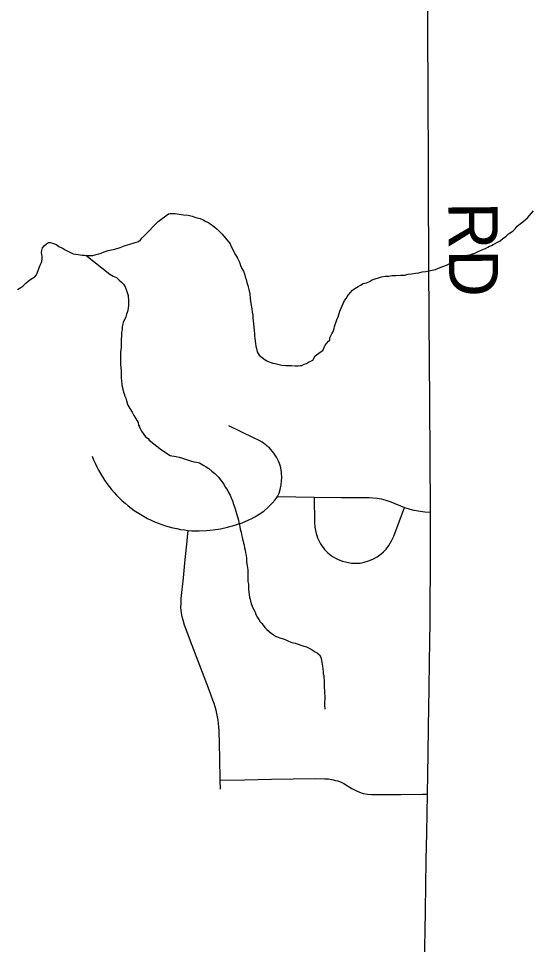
# Model space of a CAD drawing. Extents: x 103424 to 286016, y 38711 to 110967.
# Drawn here: x 131934 to 135093, y 58236 to 63924 of the extents above; entities that cross this region are included whole.
import ezdxf

# ---------------------------------------------------------------- set-up
doc = ezdxf.new("R2010")
doc.units = 0
for name, color, linetype in [('GM_X_County_Road', 7, 'Continuous'), ('GM_X_County_Road_Text', 7, 'Continuous'), ('GM_X_Minor_River', 7, 'Continuous'), ('GM_X_Township_Road', 7, 'Continuous')]:
    doc.layers.add(name, color=color, linetype=linetype)

msp = doc.modelspace()

# ---------------------------------------------------------------- linework, layer by layer
at = {"layer": 'GM_X_County_Road'}
msp.add_lwpolyline([(134429, 58147.9), (134432.1, 58313), (134434.6, 58452.5), (134437.2, 58591.9), (134440, 58757), (134442.8, 58922), (134444.8, 59040.6), (134446.8, 59159.2), (134448.9, 59283.3), (134451, 59407.3), (134453.7, 59572.4), (134455.7, 59690.3), (134457.7, 59808.2), (134460, 59973.2), (134461.8, 60095.1), (134463.5, 60217.1), (134464.5, 60363.3), (134465.4, 60509.6), (134466, 60621.2), (134466.7, 60732.8), (134465.5, 60892.6), (134463.9, 61242.9), (134463.2, 61345.7), (134462.4, 61448.6), (134461.1, 61613.7), (134459.7, 61778.7), (134458.8, 61890.9), (134457.9, 62003.1), (134457, 62168.2), (134456.1, 62333.2), (134455.4, 62448.8), (134454.8, 62564.3), (134454.3, 62729.4), (134453.9, 62894.5), (134453.4, 63059.5), (134452, 63420), (134451.1, 63576.4), (134450.3, 63732.7), (134448.5, 63892.5), (134446.7, 64052.2)], dxfattribs=at)
at = {"layer": 'GM_X_Minor_River'}
for points in [[(133937.8, 62191), (133949.7, 62205.4), (133953.5, 62215.6), (133961.3, 62225.9), (133971.2, 62238.2), (133987, 62254.7), (134000.9, 62265.1), (134010.9, 62271.4), (134020.9, 62277.7), (134034.8, 62286), (134052.8, 62296.5), (134072.9, 62301), (134090.9, 62309.5), (134106.9, 62317.9), (134165.1, 62337.3), (134187.3, 62341.9), (134209.5, 62342.3), (134229.6, 62344.8), (134251.9, 62345.3), (134284.1, 62348), (134306.4, 62348.5), (134328.5, 62353), (134350.7, 62355.5), (134372.8, 62360), (134395, 62362.5), (134415.1, 62367), (134437.3, 62369.5), (134455.4, 62373.9), (134475.5, 62378.4), (134495.6, 62382.9), (134515.7, 62391.4), (134541.7, 62400), (134563.8, 62408.6), (134587.8, 62421.2), (134611.8, 62431.8), (134635.8, 62442.5), (134659.9, 62453.1), (134681.9, 62461.6), (134701.9, 62470.1), (134718, 62476.6), (134738, 62483), (134754, 62491.5), (134778.1, 62500.1), (134792.1, 62506.4), (134804.2, 62510.7), (134818.1, 62519.1), (134828.1, 62525.4), (134840.1, 62529.7), (134850.1, 62536), (134864.1, 62542.3), (134878.1, 62550.7), (134894.1, 62559.1), (134909.9, 62573.6), (134929.9, 62586.2), (134945.7, 62600.6), (134961.7, 62611.1), (134973.6, 62619.4), (134985.5, 62631.8), (134999.3, 62648.2), (135017.2, 62662.8), (135033.1, 62675.2), (135047, 62687.6), (135060.9, 62700.1), (135098.3, 62743.3)], [(131928, 62259.7), (131948, 62272.1), (131960, 62280.4), (131977.8, 62298.9), (131993.8, 62311.3), (132003.7, 62319.5), (132019.7, 62329.9), (132031.7, 62336.1), (132043.6, 62350.5), (132066.8, 62409.4), (132072.6, 62421.7), (132076.5, 62431.8), (132078.2, 62450), (132078, 62462.2), (132077.8, 62474.3), (132075.6, 62486.4), (132077.4, 62498.5), (132081.2, 62514.7), (132091.1, 62527), (132105, 62539.4), (132117, 62547.6), (132129.1, 62547.9), (132143.3, 62544), (132155.4, 62540.2), (132169.6, 62534.4), (132181.9, 62524.5), (132196.2, 62516.6), (132208.4, 62510.8), (132220.6, 62502.9), (132232.8, 62497), (132245, 62491.2), (132257.2, 62485.3), (132269.4, 62479.4), (132283.6, 62475.6), (132299.8, 62473.9), (132324.1, 62470.2), (132338.2, 62470.5), (132354.4, 62468.7), (132370.5, 62469), (132380.6, 62469.1), (132390.7, 62469.3), (132410.8, 62473.7), (132426.9, 62478), (132440.9, 62482.3), (132459, 62490.6), (132485, 62499.1), (132525.3, 62507.9), (132557.4, 62518.5), (132589.5, 62529.1), (132617.6, 62537.7), (132671.8, 62554.7), (132683.7, 62565), (132693.6, 62577.3), (132705.5, 62589.6), (132792.5, 62676.8)], [(132792.5, 62676.8), (132855.2, 62724.8), (132865.3, 62727), (132877.4, 62727.3), (132895.6, 62725.7), (132920, 62722.1), (132948.3, 62718.7), (132976.7, 62715.3), (133001.1, 62709.8), (133023.5, 62702.2), (133049.9, 62694.7), (133068.3, 62687), (133084.6, 62677.3), (133100.9, 62671.6), (133111.2, 62663.7), (133123.5, 62653.9), (133140, 62642.1), (133154.4, 62630.3), (133168.8, 62616.5), (133183.3, 62600.7), (133197.8, 62584.8), (133214.4, 62565), (133226.8, 62551.1), (133235.1, 62539.2), (133241.5, 62523.2), (133250, 62505.2), (133258.5, 62487.2), (133266.9, 62473.3), (133273.2, 62461.3), (133279.4, 62451.3), (133285.8, 62439.4), (133292.1, 62427.4), (133298.6, 62407.3), (133307, 62389.3), (133315.5, 62371.4), (133321.9, 62355.3), (133326.3, 62337.3), (133332.8, 62321.3), (133337.2, 62303.2), (133343.7, 62283.1), (133348.2, 62259), (133354.8, 62232.9), (133357.5, 62204.7), (133362.2, 62174.5), (133366.9, 62140.3), (133369.4, 62120.1), (133373.8, 62102.1), (133374.1, 62085.9), (133379.4, 62029.5), (133381.9, 62007.3), (133384.3, 61987.2), (133384.6, 61973.1), (133386.9, 61961), (133387.3, 61942.9), (133389.7, 61926.8), (133392, 61910.7), (133396.4, 61896.6), (133400.8, 61876.5), (133413.4, 61856.6), (133431.9, 61840.9), (133450.4, 61827.1), (133460.6, 61821.3), (133474.9, 61815.5), (133485.1, 61811.7), (133497.3, 61807.9), (133511.5, 61804.2), (133527.8, 61800.5), (133552.1, 61795), (133576.4, 61793.5), (133610.8, 61792.2), (133633.1, 61790.7), (133653.3, 61791.2), (133665.4, 61793.4), (133675.5, 61793.7), (133689.5, 61800), (133703.5, 61804.4), (133715.5, 61812.7), (133729.5, 61819.1), (133743.5, 61825.4), (133757.1, 61852), (133786.9, 61874.8), (133804.9, 61885.3), (133818.3, 61917.9), (133838, 61942.6), (133848, 61948.8), (133847.7, 61963), (133859.3, 61987.4), (133865.1, 61997.7), (133869, 62007.8), (133872.8, 62020), (133876.5, 62032.2), (133880.3, 62044.4), (133886, 62060.7), (133891.7, 62079), (133897.5, 62091.2), (133903.3, 62105.5), (133908.9, 62125.8), (133916.6, 62144.2), (133922.4, 62158.4), (133930.1, 62176.8), (133937.8, 62191)], [(132347.4, 62469.5), (132495.5, 62353.8), (132515.9, 62342.1), (132536.3, 62332.3), (132552.7, 62316.4), (132567, 62304.5), (132579.3, 62292.6), (132589.7, 62276.6), (132596, 62258.5), (132606.7, 62222.3), (132606.9, 62212.2), (132609.1, 62198.1), (132609.4, 62179.9), (132609.8, 62161.8), (132608, 62147.6), (132606.2, 62131.4), (132602.4, 62119.2), (132596.5, 62107), (132592.8, 62090.8), (132585, 62072.5), (132577.2, 62058.2), (132575.4, 62046), (132571.6, 62029.8), (132569.9, 62011.6), (132566.1, 61995.4), (132566.5, 61975.2), (132564.8, 61952.9), (132565.2, 61928.7), (132563.6, 61902.4), (132560.1, 61874.1), (132560.6, 61841.8), (132561.3, 61803.4), (132561.7, 61777.1), (132564, 61763), (132564.2, 61748.9), (132564.4, 61734.7), (132564.8, 61714.5), (132567.1, 61698.4), (132569.5, 61674.2), (132571.8, 61654), (132576.1, 61640), (132578.3, 61627.9), (132582.5, 61617.9), (132586.8, 61603.8), (132593.1, 61591.8), (132597.4, 61575.7), (132605.9, 61549.5), (132618.3, 61529.5), (132632.8, 61505.5), (132643.3, 61485.5), (132653.6, 61469.5), (132662, 61453.5), (132668.2, 61443.5), (132670.5, 61425.3), (132676.7, 61415.3), (132680.9, 61405.3), (132689.3, 61389.3), (132714.1, 61355.3), (132730.4, 61343.5), (132736.6, 61333.5), (132811.9, 61273.7)], [(132811.9, 61273.7), (132864.7, 61239), (132876.9, 61237.2), (132891, 61235.5), (132903.2, 61233.7), (132921.5, 61230.1), (132941.8, 61222.5), (132966.3, 61214.9), (132990.7, 61207.4), (133011, 61201.8), (133029.3, 61198.1), (133045.5, 61194.4), (133055.8, 61188.6), (133072.1, 61178.8), (133086.4, 61171.1), (133102.9, 61159.3), (133121.4, 61143.6), (133139.9, 61129.8), (133154.3, 61116), (133164.7, 61104.1), (133173, 61092.2), (133181.3, 61082.3), (133195.8, 61064.4), (133204.3, 61046.4), (133216.8, 61030.6), (133225.2, 61012.6), (133233.7, 60996.6), (133240.1, 60980.6), (133248.6, 60960.6), (133255.1, 60940.5), (133263.6, 60918.5), (133270.1, 60898.5), (133285.5, 60842.3), (133287.8, 60826.2), (133292.1, 60814.1), (133294.4, 60802.1), (133296.7, 60788), (133301.2, 60769.9), (133303.5, 60753.8), (133307.9, 60737.8), (133310.2, 60725.7), (133314.5, 60713.7), (133316.7, 60701.6), (133321.1, 60689.6), (133323.4, 60673.5), (133325.7, 60659.4), (133328.2, 60641.3), (133332.5, 60625.2), (133334.9, 60609.1), (133335.3, 60588.9), (133337.6, 60574.9), (133339.9, 60562.8), (133340.2, 60550.7), (133342.5, 60538.6), (133342.9, 60518.4), (133343.2, 60506.3), (133343.6, 60484.1), (133344, 60466), (133346.4, 60449.9), (133346.7, 60435.7), (133347.1, 60417.6), (133349.4, 60401.5), (133351.8, 60383.4), (133354.2, 60369.3), (133356.4, 60357.2), (133358.7, 60345.2), (133365.2, 60325.1), (133373.7, 60305.1), (133382.1, 60289.1), (133388.5, 60277.2), (133392.8, 60263.1), (133403.3, 60245.2), (133409.6, 60233.2), (133418, 60217.2), (133428.4, 60207.3), (133436.7, 60197.4), (133447, 60183.5), (133459.4, 60171.7), (133475.9, 60155.9), (133492.4, 60144.1), (133517, 60128.5), (133545.5, 60117), (133567.8, 60111.4), (133580.1, 60105.7), (133592.3, 60099.9), (133612.7, 60092.2), (133633, 60086.6), (133651.4, 60081), (133669.7, 60075.3), (133688, 60069.6), (133704.3, 60063.9), (133720.6, 60056.2), (133739, 60046.5), (133757.4, 60034.8), (133771.8, 60025), (133784.1, 60015.2), (133792.5, 60001.2), (133797.2, 59971.1), (133801.8, 59944.9), (133804.2, 59928.8), (133806.5, 59912.7)], [(133806.5, 59912.7), (133806.8, 59898.6), (133809.1, 59888.5), (133809.3, 59876.4), (133811.8, 59856.3), (133812.1, 59842.2), (133812.4, 59828), (133812.7, 59811.9), (133815.1, 59795.8), (133813.4, 59781.6), (133815.8, 59761.5), (133816.2, 59743.3), (133814.5, 59727.1), (133814.8, 59713), (133815.1, 59700.9), (133815.3, 59688.8), (133815.5, 59682.7)]]:
    msp.add_lwpolyline(points, dxfattribs=at)
at = {"layer": 'GM_X_Township_Road'}
for points in [[(132386.5, 61236.2), (132395.3, 61214), (132404.6, 61192.2), (132414.6, 61170.6), (132425.4, 61149.4), (132437, 61128.6), (132449.3, 61108.2), (132462.4, 61088.2), (132476, 61068.6), (132490.1, 61049.5), (132505.2, 61031), (132520.6, 61012.9), (132536.6, 60995.3), (132553.5, 60978.4), (132570.6, 60962), (132588.5, 60946.2), (132606.9, 60931), (132625.7, 60916.4), (132645.1, 60902.5), (132664.7, 60889.2), (132685.1, 60876.6), (132705.7, 60864.7), (132726.6, 60853.5), (132748, 60843.1), (132769.9, 60833.3), (132791.8, 60824.3), (132814.2, 60816), (132836.9, 60808.5), (132859.8, 60801.8), (132882.7, 60795.9), (132906.1, 60790.6), (132929.5, 60786.3), (132952.9, 60782.7), (132976.5, 60779.9), (132998.9, 60778), (133021.6, 60776.8), (133044, 60776.3), (133089.9, 60778.2), (133129.9, 60782.7), (133174.2, 60789.9), (133217.9, 60798.8), (133262.9, 60811.6), (133307.8, 60826.2), (133349.1, 60844.1), (133368, 60853.4), (133386.9, 60863.3), (133413.6, 60879.7), (133440.4, 60898.7), (133466.2, 60920.8), (133490.9, 60945.2), (133510.3, 60968.1), (133524.9, 60987.8), (133535.4, 61009.4), (133542, 61031), (133547.2, 61060.5), (133550.5, 61084.7), (133551.7, 61103.1), (133550.7, 61136.4), (133548.4, 61150.5), (133545.4, 61164.4), (133541.6, 61178.1), (133537.1, 61191.6), (133531.8, 61204.8), (133525.8, 61217.8), (133519, 61230.3), (133511.4, 61242.4), (133503.4, 61254.1), (133494.6, 61265.3), (133485.3, 61276), (133475.2, 61286.2), (133464.6, 61295.7), (133453.6, 61304.7), (133442.2, 61313.1), (133430.2, 61320.8), (133412.3, 61331.1), (133378.2, 61348.1), (133302.5, 61384.8), (133226.9, 61421.5)], [(133524.9, 60987.8), (133638.3, 60985.5), (133751.6, 60983.2), (133916.7, 60982.1), (134003, 60981.5), (134089.4, 60980.9), (134111.3, 60980), (134138.3, 60977.3), (134163, 60973.2), (134190.7, 60966.1), (134221.3, 60956), (134306.9, 60920.1), (134352.3, 60906.7), (134389, 60899), (134430.2, 60894.8), (134465.5, 60892.6)], [(133751.6, 60983.2), (133752, 60827.7), (133754.6, 60798.9), (133757.9, 60779.2), (133762.4, 60761.3), (133766.4, 60747.8), (133771.2, 60734.6), (133776.7, 60721.7), (133783, 60709.2), (133790.1, 60696.9), (133797.9, 60685.2), (133806.2, 60673.8), (133815, 60662.9), (133824.5, 60652.6), (133834.6, 60642.8), (133845.2, 60633.5), (133856.2, 60625), (133867.8, 60617), (133880.9, 60608.8), (133898.6, 60600.5), (133925, 60591.2), (133951.8, 60584), (133979.3, 60579.4), (134004.8, 60577.8), (134033.2, 60579.4), (134058.6, 60584), (134085.2, 60592.3), (134112.3, 60602.3), (134138.9, 60617.2), (134161.2, 60632.9), (134177.2, 60647.6), (134193.3, 60665.3), (134209.9, 60687.5), (134225.9, 60715.9), (134240.1, 60744.5), (134267.6, 60815.3), (134306.9, 60920.1)], [(133174.2, 59191.2), (133173.3, 59246.2), (133169.9, 59381.6), (133168.2, 59466.6), (133166.5, 59551.7), (133165.2, 59572.8), (133163, 59593.7), (133160.2, 59614.6), (133156.7, 59635.4), (133152.5, 59656.1), (133147.4, 59676.5), (133141.7, 59696.8), (133135.4, 59716.9), (133128.1, 59736.8), (133107, 59794.8), (133048.3, 59949.1), (133001.2, 60072.9), (132954.1, 60196.8), (132944.6, 60229), (132940.1, 60248), (132934.8, 60273.9), (132932, 60305.7), (132932.7, 60333.1), (132934, 60362), (132947, 60487.8), (132958.3, 60600.4), (132969.7, 60713), (132972.5, 60740.1), (132976.5, 60779.9)], [(133173.3, 59246.2), (133323.1, 59248.6), (133488.1, 59251.1), (133622.1, 59253.2), (133756.1, 59255.3), (133816.8, 59254.5), (133838.1, 59252.9), (133860.2, 59249.7), (133882.2, 59244.4), (133895.3, 59240.6), (133920.5, 59231), (133932.8, 59225.2), (133956.2, 59211.6), (133982.9, 59195), (134007.6, 59181.8), (134029, 59171.3), (134052.4, 59163.3), (134077.9, 59159), (134102.4, 59157.4), (134150.5, 59156.7), (134283.5, 59157.7), (134416.6, 59158.9), (134446.8, 59159.2)]]:
    msp.add_lwpolyline(points, dxfattribs=at)

# ---------------------------------------------------------------- texts
at = {"layer": 'GM_X_County_Road_Text'}
msp.add_text('RD', height=301.87, rotation=270.4937, dxfattribs=at).set_placement((134575.8, 62796.1))

doc.saveas('drawing.dxf')
